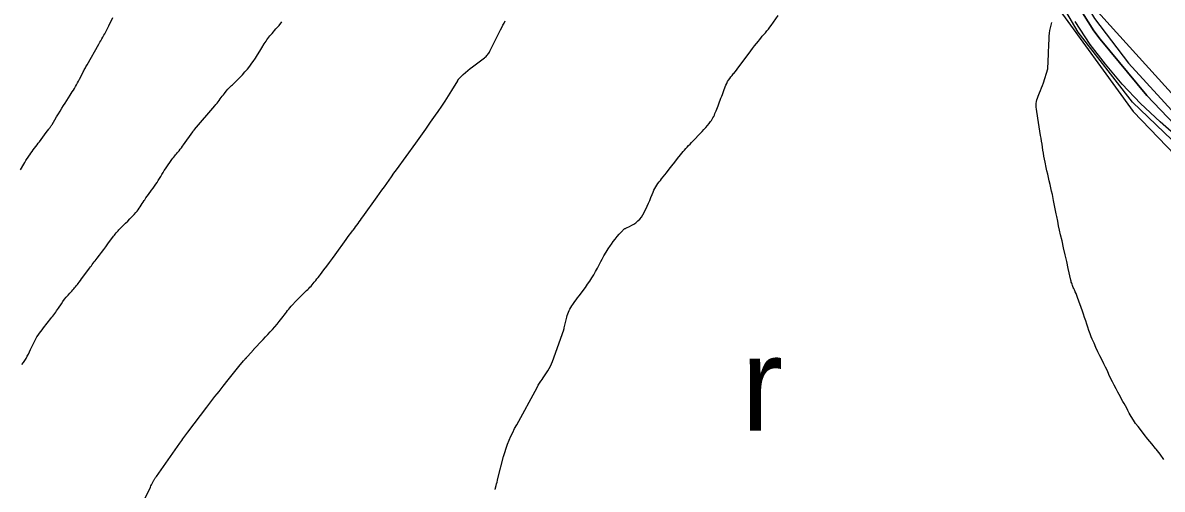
# Model space of a CAD drawing. Extents: x -629976 to -626966, y -1086511 to -1082952.
# Drawn here: x -629290.8 to -629035.3, y -1086079 to -1085974.4 of the extents above; entities that cross this region are included whole.
import ezdxf

# ---------------------------------------------------------------- set-up
doc = ezdxf.new("R2010")
doc.units = 0
for name, color, linetype in [('01_OBVOD PÚ', 7, 'Continuous'), ('01_PARCELY_NÁVRH_PC', 7, 'Continuous'), ('01_VRSTEVNICE', 7, 'Continuous'), ('02_KULTURY STAV', 7, 'Continuous'), ('03_PC_NÁVRH', 7, 'Continuous'), ('03_PC_OBJEKTY_NÁVRH', 7, 'Continuous'), ('04_ZPF_OP_ORGAN', 7, 'Continuous'), ('05_VHO_OPVZ', 7, 'Continuous')]:
    doc.layers.add(name, color=color, linetype=linetype)

msp = doc.modelspace()

# ---------------------------------------------------------------- linework, layer by layer
at = {"layer": '01_OBVOD PÚ'}
msp.add_lwpolyline([(-629150.28, -1085765.65), (-629148.72, -1085805.48), (-629141.31, -1085833.59), (-629128.11, -1085853.02), (-629125.94, -1085855.15), (-629104.39, -1085877.56), (-629101.39, -1085880.01), (-629093.2, -1085885.54), (-629081.1, -1085905.64), (-629071.96, -1085919.41), (-629058.85, -1085946.7), (-629049.68, -1085971.97), (-629047.7, -1085974.15), (-629031.77, -1085991.7), (-629013.43, -1086008.55), (-628996.23, -1086021.54), (-628982.57, -1086033.23), (-628979.99, -1086035.43), (-628963.86, -1086049.23), (-628947.04, -1086060.41), (-628925.53, -1086073.14), (-628892, -1086083.87)], dxfattribs=at)
at = {"layer": '01_PARCELY_NÁVRH_PC'}
for points in [[(-629011.89, -1086017.6), (-629035.76, -1085996.56), (-629040.17, -1085992.44), (-629044.28, -1085988.11), (-629048.06, -1085983.67), (-629051.43, -1085979.21), (-629054.85, -1085974.1)], [(-629047.7, -1085974.15), (-629031.77, -1085991.7)]]:
    msp.add_lwpolyline(points, dxfattribs=at)
at = {"layer": '01_VRSTEVNICE'}
for points in [[(-629291.33, -1086007.3), (-629290.62, -1086006.09), (-629290.37, -1086005.66), (-629290.11, -1086005.24), (-629289.84, -1086004.82), (-629289.57, -1086004.41), (-629289.53, -1086004.35), (-629289.27, -1086003.97), (-629289, -1086003.59), (-629288.73, -1086003.21), (-629288.46, -1086002.84), (-629288.18, -1086002.47), (-629287.91, -1086002.09), (-629287.63, -1086001.72), (-629287.35, -1086001.35), (-629287.1, -1086001.03), (-629286.71, -1086000.52), (-629286.33, -1086000.01), (-629285.94, -1085999.49), (-629285.56, -1085998.98), (-629284.98, -1085998.22), (-629284.88, -1085998.09), (-629284.79, -1085997.95), (-629284.69, -1085997.82), (-629284.6, -1085997.69), (-629284.51, -1085997.55), (-629284.42, -1085997.42), (-629284.34, -1085997.28), (-629284.25, -1085997.14), (-629283.63, -1085996.11), (-629283.24, -1085995.46), (-629282.84, -1085994.8), (-629282.44, -1085994.15), (-629282.04, -1085993.5), (-629281.69, -1085992.94), (-629281.32, -1085992.36), (-629280.95, -1085991.78), (-629280.58, -1085991.2), (-629280.21, -1085990.62), (-629279.97, -1085990.25), (-629279.72, -1085989.86), (-629279.47, -1085989.46), (-629279.22, -1085989.06), (-629278.98, -1085988.65), (-629278.75, -1085988.25), (-629278.52, -1085987.83), (-629278.3, -1085987.42), (-629278.09, -1085987), (-629277.38, -1085985.6), (-629277.27, -1085985.37), (-629277.15, -1085985.14), (-629277.03, -1085984.92), (-629276.91, -1085984.69), (-629276.79, -1085984.47), (-629276.67, -1085984.24), (-629276.55, -1085984.02), (-629276.42, -1085983.8), (-629273.76, -1085979.12), (-629273.55, -1085978.74), (-629273.33, -1085978.37), (-629273.11, -1085977.99), (-629272.89, -1085977.61), (-629272.8, -1085977.44), (-629272.63, -1085977.15), (-629272.46, -1085976.85), (-629272.29, -1085976.55), (-629272.12, -1085976.25), (-629271.96, -1085975.95), (-629271.8, -1085975.65), (-629271.65, -1085975.35), (-629271.5, -1085975.04), (-629270.6, -1085973.17)], [(-629291.01, -1086051.01), (-629290.68, -1086050.57), (-629290.37, -1086050.11), (-629290.09, -1086049.64), (-629289.82, -1086049.15), (-629289.57, -1086048.66), (-629289.33, -1086048.16), (-629289.09, -1086047.66), (-629288.85, -1086047.16), (-629288.37, -1086046.13), (-629288.15, -1086045.68), (-629287.91, -1086045.24), (-629287.65, -1086044.81), (-629287.38, -1086044.4), (-629287.1, -1086043.99), (-629286.81, -1086043.58), (-629286.5, -1086043.18), (-629286.2, -1086042.79), (-629284.5, -1086040.69), (-629284.28, -1086040.41), (-629284.06, -1086040.12), (-629283.85, -1086039.83), (-629283.65, -1086039.54), (-629283.44, -1086039.24), (-629283.24, -1086038.94), (-629283.04, -1086038.64), (-629282.84, -1086038.34), (-629282.16, -1086037.35), (-629281.81, -1086036.85), (-629281.44, -1086036.36), (-629281.06, -1086035.89), (-629280.66, -1086035.42), (-629280.27, -1086034.99), (-629280.06, -1086034.75), (-629279.84, -1086034.51), (-629279.62, -1086034.27), (-629279.41, -1086034.04), (-629279.19, -1086033.8), (-629278.98, -1086033.56), (-629278.78, -1086033.31), (-629278.58, -1086033.06), (-629278.43, -1086032.86), (-629278.16, -1086032.5), (-629277.9, -1086032.14), (-629277.63, -1086031.79), (-629277.37, -1086031.43), (-629275.88, -1086029.4), (-629275.66, -1086029.12), (-629275.45, -1086028.83), (-629275.23, -1086028.56), (-629275.01, -1086028.28), (-629274.79, -1086028), (-629274.57, -1086027.72), (-629274.36, -1086027.44), (-629274.14, -1086027.16), (-629273.62, -1086026.47), (-629273.14, -1086025.84), (-629272.67, -1086025.21), (-629272.2, -1086024.58), (-629271.73, -1086023.95), (-629270.47, -1086022.23), (-629270.28, -1086021.98), (-629270.08, -1086021.73), (-629269.88, -1086021.49), (-629269.68, -1086021.25), (-629269.47, -1086021.02), (-629269.26, -1086020.79), (-629269.04, -1086020.56), (-629268.82, -1086020.34), (-629267.77, -1086019.3), (-629267.28, -1086018.81), (-629266.8, -1086018.32), (-629266.32, -1086017.82), (-629265.85, -1086017.32), (-629265.48, -1086016.92), (-629265.21, -1086016.6), (-629264.95, -1086016.28), (-629264.7, -1086015.95), (-629264.47, -1086015.6), (-629264.25, -1086015.25), (-629264.02, -1086014.9), (-629263.8, -1086014.55), (-629263.57, -1086014.2), (-629263.48, -1086014.06), (-629263.21, -1086013.64), (-629262.92, -1086013.23), (-629262.63, -1086012.83), (-629262.33, -1086012.43), (-629262.27, -1086012.35), (-629261.93, -1086011.92), (-629261.61, -1086011.48), (-629261.29, -1086011.03), (-629260.99, -1086010.58), (-629260.72, -1086010.18), (-629260.44, -1086009.74), (-629260.16, -1086009.3), (-629259.9, -1086008.85), (-629259.63, -1086008.4), (-629259.37, -1086007.96), (-629259.1, -1086007.51), (-629258.81, -1086007.08), (-629258.52, -1086006.65), (-629257.57, -1086005.27), (-629257.38, -1086005), (-629257.18, -1086004.73), (-629256.97, -1086004.47), (-629256.76, -1086004.22), (-629256.54, -1086003.96), (-629256.32, -1086003.71), (-629256.11, -1086003.45), (-629255.9, -1086003.2), (-629255.78, -1086003.06), (-629255.52, -1086002.73), (-629255.26, -1086002.39), (-629255.01, -1086002.05), (-629254.76, -1086001.71), (-629252.68, -1085998.8), (-629252.66, -1085998.76), (-629252.63, -1085998.72), (-629252.6, -1085998.69), (-629252.58, -1085998.65), (-629252.55, -1085998.61), (-629252.54, -1085998.6), (-629252.53, -1085998.58), (-629252.52, -1085998.57), (-629252.51, -1085998.55), (-629252.5, -1085998.54), (-629252.49, -1085998.53), (-629252.48, -1085998.51), (-629252.47, -1085998.5), (-629252.42, -1085998.45), (-629252.39, -1085998.41), (-629252.36, -1085998.37), (-629252.33, -1085998.33), (-629252.29, -1085998.29), (-629247.75, -1085992.98), (-629247.5, -1085992.68), (-629247.26, -1085992.38), (-629247.02, -1085992.07), (-629246.79, -1085991.75), (-629246.56, -1085991.43), (-629246.33, -1085991.12), (-629246.09, -1085990.81), (-629245.85, -1085990.5), (-629245.6, -1085990.18), (-629245.23, -1085989.73), (-629244.84, -1085989.28), (-629244.43, -1085988.85), (-629244.01, -1085988.44), (-629243.8, -1085988.24), (-629243.27, -1085987.72), (-629242.74, -1085987.21), (-629242.22, -1085986.68), (-629241.71, -1085986.15), (-629241.57, -1085986.01), (-629241.01, -1085985.39), (-629240.46, -1085984.76), (-629239.94, -1085984.1), (-629239.45, -1085983.43), (-629239.16, -1085983.02), (-629238.65, -1085982.27), (-629238.16, -1085981.52), (-629237.68, -1085980.76), (-629237.21, -1085980), (-629236.67, -1085979.08), (-629236.47, -1085978.77), (-629236.28, -1085978.46), (-629236.07, -1085978.16), (-629235.85, -1085977.87), (-629235.63, -1085977.58), (-629235.4, -1085977.3), (-629235.16, -1085977.02), (-629234.92, -1085976.75), (-629234.04, -1085975.74), (-629233.36, -1085974.96), (-629232.7, -1085974.16)], [(-629263.63, -1086081.42), (-629262.22, -1086078.5), (-629262.08, -1086078.22), (-629261.94, -1086077.94), (-629261.8, -1086077.66), (-629261.66, -1086077.38), (-629261.51, -1086077.09), (-629261.44, -1086076.96), (-629261.37, -1086076.84), (-629261.29, -1086076.71), (-629261.21, -1086076.59), (-629261.12, -1086076.47), (-629261.04, -1086076.34), (-629260.95, -1086076.22), (-629260.87, -1086076.1), (-629255.58, -1086068.61), (-629255.36, -1086068.31), (-629255.14, -1086068), (-629254.93, -1086067.69), (-629254.71, -1086067.38), (-629254.49, -1086067.08), (-629254.27, -1086066.77), (-629254.05, -1086066.47), (-629253.82, -1086066.17), (-629249.56, -1086060.54), (-629249.11, -1086059.95), (-629248.65, -1086059.36), (-629248.19, -1086058.77), (-629247.73, -1086058.18), (-629247.27, -1086057.6), (-629246.81, -1086057.01), (-629246.34, -1086056.43), (-629245.88, -1086055.85), (-629244.78, -1086054.46), (-629244.18, -1086053.71), (-629243.57, -1086052.96), (-629242.97, -1086052.21), (-629242.36, -1086051.46), (-629241.3, -1086050.16), (-629241.22, -1086050.06), (-629241.14, -1086049.97), (-629241.05, -1086049.87), (-629240.97, -1086049.78), (-629240.92, -1086049.73), (-629240.86, -1086049.66), (-629240.8, -1086049.6), (-629240.74, -1086049.54), (-629240.68, -1086049.47), (-629240.62, -1086049.41), (-629240.56, -1086049.34), (-629240.51, -1086049.28), (-629240.45, -1086049.21), (-629239.04, -1086047.61), (-629238.99, -1086047.56), (-629238.95, -1086047.51), (-629238.9, -1086047.45), (-629238.85, -1086047.4), (-629238.81, -1086047.35), (-629238.76, -1086047.3), (-629238.71, -1086047.25), (-629238.66, -1086047.2), (-629237.44, -1086045.92), (-629236.91, -1086045.36), (-629236.37, -1086044.81), (-629235.85, -1086044.24), (-629235.32, -1086043.68), (-629234.8, -1086043.11), (-629234.29, -1086042.54), (-629233.8, -1086041.95), (-629233.31, -1086041.35), (-629232.7, -1086040.57), (-629232.44, -1086040.24), (-629232.19, -1086039.91), (-629231.94, -1086039.57), (-629231.69, -1086039.24), (-629231.44, -1086038.9), (-629231.19, -1086038.57), (-629230.92, -1086038.25), (-629230.64, -1086037.94), (-629229.35, -1086036.53), (-629228.92, -1086036.08), (-629228.49, -1086035.63), (-629228.04, -1086035.2), (-629227.58, -1086034.77), (-629227.2, -1086034.43), (-629226.93, -1086034.18), (-629226.67, -1086033.92), (-629226.42, -1086033.66), (-629226.17, -1086033.39), (-629225.93, -1086033.11), (-629225.69, -1086032.83), (-629225.46, -1086032.55), (-629225.23, -1086032.27), (-629225.13, -1086032.16), (-629224.86, -1086031.81), (-629224.59, -1086031.47), (-629224.32, -1086031.12), (-629224.05, -1086030.77), (-629223.29, -1086029.79), (-629222.65, -1086028.95), (-629222.01, -1086028.1), (-629221.39, -1086027.25), (-629220.77, -1086026.39), (-629218.32, -1086022.97), (-629217.97, -1086022.49), (-629217.62, -1086022.01), (-629217.26, -1086021.53), (-629216.91, -1086021.05), (-629216.74, -1086020.83), (-629216.47, -1086020.47), (-629216.19, -1086020.1), (-629215.92, -1086019.74), (-629215.64, -1086019.37), (-629215.37, -1086019), (-629215.1, -1086018.64), (-629214.83, -1086018.27), (-629214.56, -1086017.9), (-629211.35, -1086013.42), (-629210.81, -1086012.67), (-629210.27, -1086011.91), (-629209.73, -1086011.15), (-629209.19, -1086010.39), (-629208.66, -1086009.63), (-629208.12, -1086008.87), (-629207.58, -1086008.11), (-629207.04, -1086007.36), (-629202.71, -1086001.32), (-629201.59, -1085999.76), (-629200.47, -1085998.21), (-629199.36, -1085996.65), (-629198.25, -1085995.09), (-629197.64, -1085994.23), (-629196.85, -1085993.09), (-629196.08, -1085991.93), (-629195.34, -1085990.76), (-629194.62, -1085989.58), (-629193.3, -1085987.34), (-629193.25, -1085987.26), (-629193.21, -1085987.19), (-629193.16, -1085987.11), (-629193.11, -1085987.04), (-629193.06, -1085986.97), (-629193.01, -1085986.9), (-629192.95, -1085986.84), (-629192.89, -1085986.77), (-629192.04, -1085985.95), (-629191.54, -1085985.49), (-629191.03, -1085985.04), (-629190.51, -1085984.61), (-629189.97, -1085984.2), (-629187.29, -1085982.2), (-629187.1, -1085982.05), (-629186.92, -1085981.89), (-629186.75, -1085981.72), (-629186.59, -1085981.53), (-629186.44, -1085981.34), (-629186.3, -1085981.14), (-629186.18, -1085980.93), (-629186.06, -1085980.72), (-629183.93, -1085976.41), (-629183.68, -1085975.92), (-629183.43, -1085975.42), (-629183.17, -1085974.92), (-629182.91, -1085974.43), (-629182.64, -1085973.9)], [(-629184.9, -1086079), (-629184.87, -1086078.89), (-629184.84, -1086078.78), (-629184.81, -1086078.68), (-629184.67, -1086078.12), (-629184.57, -1086077.73), (-629184.47, -1086077.35), (-629184.38, -1086076.96), (-629184.28, -1086076.58), (-629183.01, -1086071.64), (-629182.75, -1086070.7), (-629182.46, -1086069.78), (-629182.13, -1086068.87), (-629181.77, -1086067.97), (-629181.37, -1086067.09), (-629180.96, -1086066.21), (-629180.52, -1086065.35), (-629180.07, -1086064.49), (-629175.49, -1086056.15), (-629175.22, -1086055.66), (-629174.93, -1086055.18), (-629174.62, -1086054.71), (-629174.3, -1086054.25), (-629174.29, -1086054.23), (-629173.98, -1086053.78), (-629173.67, -1086053.33), (-629173.37, -1086052.88), (-629173.08, -1086052.42), (-629173.05, -1086052.38), (-629172.76, -1086051.88), (-629172.5, -1086051.38), (-629172.27, -1086050.86), (-629172.06, -1086050.34), (-629169.51, -1086043.21), (-629169.49, -1086043.16), (-629169.47, -1086043.1), (-629169.46, -1086043.05), (-629169.44, -1086042.99), (-629169.43, -1086042.94), (-629169.42, -1086042.88), (-629169.4, -1086042.82), (-629169.39, -1086042.77), (-629168.85, -1086040.41), (-629168.75, -1086040.02), (-629168.63, -1086039.64), (-629168.48, -1086039.27), (-629168.32, -1086038.9), (-629168.13, -1086038.55), (-629167.94, -1086038.2), (-629167.72, -1086037.86), (-629167.49, -1086037.53), (-629167.34, -1086037.32), (-629167.03, -1086036.89), (-629166.71, -1086036.47), (-629166.4, -1086036.04), (-629166.08, -1086035.61), (-629164.65, -1086033.7), (-629164.16, -1086033.01), (-629163.68, -1086032.31), (-629163.23, -1086031.59), (-629162.8, -1086030.86), (-629162.39, -1086030.12), (-629161.98, -1086029.38), (-629161.58, -1086028.64), (-629161.18, -1086027.89), (-629160.92, -1086027.4), (-629160.49, -1086026.61), (-629160.03, -1086025.83), (-629159.55, -1086025.07), (-629159.05, -1086024.33), (-629158.82, -1086024.01), (-629158.41, -1086023.44), (-629157.98, -1086022.87), (-629157.53, -1086022.32), (-629157.07, -1086021.78), (-629156.29, -1086020.91), (-629156.2, -1086020.82), (-629156.11, -1086020.74), (-629156.01, -1086020.66), (-629155.91, -1086020.59), (-629155.8, -1086020.52), (-629155.7, -1086020.46), (-629155.59, -1086020.4), (-629155.47, -1086020.35), (-629154.73, -1086020.02), (-629154.26, -1086019.78), (-629153.81, -1086019.52), (-629153.38, -1086019.21), (-629152.98, -1086018.87), (-629152.89, -1086018.79), (-629152.48, -1086018.37), (-629152.11, -1086017.93), (-629151.79, -1086017.44), (-629151.51, -1086016.93), (-629150.84, -1086015.5), (-629150.54, -1086014.84), (-629150.24, -1086014.18), (-629149.96, -1086013.51), (-629149.69, -1086012.84), (-629149.48, -1086012.31), (-629149.3, -1086011.91), (-629149.11, -1086011.51), (-629148.88, -1086011.13), (-629148.64, -1086010.77), (-629148.38, -1086010.41), (-629148.11, -1086010.05), (-629147.84, -1086009.7), (-629147.57, -1086009.35), (-629146.48, -1086007.98), (-629145.86, -1086007.19), (-629145.24, -1086006.41), (-629144.62, -1086005.62), (-629144, -1086004.83), (-629143.34, -1086003.97), (-629143.05, -1086003.61), (-629142.76, -1086003.26), (-629142.45, -1086002.91), (-629142.14, -1086002.57), (-629141.82, -1086002.24), (-629141.51, -1086001.91), (-629141.19, -1086001.57), (-629140.87, -1086001.24), (-629138.48, -1085998.75), (-629138.07, -1085998.31), (-629137.67, -1085997.86), (-629137.29, -1085997.4), (-629136.92, -1085996.93), (-629136.61, -1085996.52), (-629136.41, -1085996.24), (-629136.22, -1085995.95), (-629136.05, -1085995.65), (-629135.89, -1085995.35), (-629135.74, -1085995.04), (-629135.6, -1085994.72), (-629135.47, -1085994.4), (-629135.34, -1085994.09), (-629134.89, -1085992.96), (-629134.73, -1085992.54), (-629134.56, -1085992.12), (-629134.4, -1085991.7), (-629134.25, -1085991.27), (-629134.09, -1085990.85), (-629133.93, -1085990.43), (-629133.78, -1085990.01), (-629133.62, -1085989.58), (-629133.31, -1085988.72), (-629133.15, -1085988.33), (-629132.97, -1085987.94), (-629132.76, -1085987.56), (-629132.54, -1085987.2), (-629132.29, -1085986.84), (-629132.04, -1085986.49), (-629131.77, -1085986.16), (-629131.49, -1085985.83), (-629131.4, -1085985.73), (-629131.07, -1085985.35), (-629130.76, -1085984.97), (-629130.45, -1085984.57), (-629130.15, -1085984.17), (-629127.58, -1085980.65), (-629127.17, -1085980.09), (-629126.74, -1085979.54), (-629126.31, -1085978.99), (-629125.87, -1085978.45), (-629125.65, -1085978.18), (-629125.31, -1085977.78), (-629124.98, -1085977.38), (-629124.64, -1085976.98), (-629124.3, -1085976.59), (-629123.96, -1085976.19), (-629123.63, -1085975.78), (-629123.31, -1085975.36), (-629123, -1085974.94), (-629121.4, -1085972.71)], [(-629034.92, -1086072.29), (-629035.79, -1086071.13), (-629036.68, -1086069.98), (-629036.82, -1086069.8), (-629037.66, -1086068.76), (-629038.5, -1086067.71), (-629039.34, -1086066.65), (-629040.18, -1086065.6), (-629040.72, -1086064.92), (-629041.26, -1086064.2), (-629041.78, -1086063.45), (-629042.25, -1086062.68), (-629042.69, -1086061.89), (-629042.99, -1086061.34), (-629043.26, -1086060.81), (-629043.54, -1086060.29), (-629043.83, -1086059.77), (-629044.12, -1086059.25), (-629044.4, -1086058.73), (-629044.69, -1086058.21), (-629044.97, -1086057.69), (-629045.26, -1086057.16), (-629045.66, -1086056.42), (-629046.08, -1086055.63), (-629046.48, -1086054.84), (-629046.87, -1086054.04), (-629047.24, -1086053.23), (-629047.61, -1086052.43), (-629047.99, -1086051.62), (-629048.38, -1086050.82), (-629048.78, -1086050.03), (-629049.28, -1086049.04), (-629049.73, -1086048.12), (-629050.17, -1086047.18), (-629050.59, -1086046.24), (-629051, -1086045.29), (-629051.21, -1086044.8), (-629051.49, -1086044.09), (-629051.76, -1086043.37), (-629052.01, -1086042.65), (-629052.24, -1086041.92), (-629052.47, -1086041.19), (-629052.71, -1086040.46), (-629052.95, -1086039.73), (-629053.21, -1086039.01), (-629054.3, -1086035.94), (-629054.46, -1086035.52), (-629054.62, -1086035.1), (-629054.8, -1086034.69), (-629054.98, -1086034.28), (-629055.15, -1086033.93), (-629055.25, -1086033.7), (-629055.35, -1086033.47), (-629055.44, -1086033.24), (-629055.53, -1086033), (-629055.61, -1086032.76), (-629055.69, -1086032.52), (-629055.75, -1086032.28), (-629055.81, -1086032.04), (-629056.38, -1086029.45), (-629056.72, -1086027.91), (-629057.07, -1086026.37), (-629057.41, -1086024.83), (-629057.76, -1086023.29), (-629058.08, -1086021.93), (-629058.31, -1086020.9), (-629058.54, -1086019.86), (-629058.75, -1086018.83), (-629058.97, -1086017.79), (-629059.09, -1086017.18), (-629059.24, -1086016.44), (-629059.39, -1086015.71), (-629059.53, -1086014.97), (-629059.68, -1086014.23), (-629059.94, -1086012.89), (-629060.1, -1086012.12), (-629060.26, -1086011.36), (-629060.44, -1086010.59), (-629060.62, -1086009.83), (-629060.8, -1086009.07), (-629060.98, -1086008.31), (-629061.16, -1086007.55), (-629061.33, -1086006.78), (-629061.58, -1086005.63), (-629061.72, -1086004.96), (-629061.85, -1086004.29), (-629061.96, -1086003.62), (-629062.06, -1086002.95), (-629062.16, -1086002.27), (-629062.26, -1086001.6), (-629062.36, -1086000.93), (-629062.47, -1086000.26), (-629062.57, -1085999.65), (-629062.74, -1085998.67), (-629062.9, -1085997.69), (-629063.05, -1085996.71), (-629063.2, -1085995.73), (-629063.52, -1085993.7), (-629063.56, -1085993.28), (-629063.57, -1085992.87), (-629063.55, -1085992.45), (-629063.49, -1085992.04), (-629063.4, -1085991.63), (-629063.29, -1085991.23), (-629063.15, -1085990.83), (-629062.99, -1085990.44), (-629062.84, -1085990.09), (-629062.59, -1085989.53), (-629062.36, -1085988.97), (-629062.16, -1085988.39), (-629061.96, -1085987.81), (-629060.98, -1085984.67), (-629060.98, -1085984.66), (-629060.97, -1085984.66), (-629060.97, -1085984.65), (-629060.97, -1085984.64), (-629060.96, -1085984.63), (-629060.96, -1085984.62), (-629060.96, -1085984.61), (-629060.96, -1085984.6), (-629060.96, -1085984.59), (-629060.96, -1085984.59), (-629060.96, -1085984.58), (-629060.81, -1085981.38), (-629060.78, -1085980.6), (-629060.75, -1085979.83), (-629060.72, -1085979.05), (-629060.69, -1085978.27), (-629060.68, -1085977.96), (-629060.65, -1085977.34), (-629060.59, -1085976.72), (-629060.49, -1085976.1), (-629060.37, -1085975.49), (-629060.22, -1085974.88), (-629060.04, -1085974.28)]]:
    msp.add_lwpolyline(points, dxfattribs=at)
at = {"layer": '02_KULTURY STAV'}
for points in [[(-629315.26, -1085933.92), (-629290.08, -1085888.82), (-629270.79, -1085881.81), (-629263.62, -1085878.44), (-629256.36, -1085875.28), (-629248.54, -1085873.03), (-629222.32, -1085865.34), (-629205.81, -1085859.65), (-629187.37, -1085853.31), (-629177.06, -1085850.52), (-629170.23, -1085849.64), (-629153.55, -1085848.3), (-629142.1, -1085849.52), (-629132.11, -1085854.87), (-629103.36, -1085887.17), (-629090.79, -1085901.96), (-629084.11, -1085913.46), (-629066.15, -1085950.26), (-629060.06, -1085961.14), (-629050.66, -1085976.16), (-629049.21, -1085978), (-629038.79, -1085990.64), (-629026.26, -1086003.71)], [(-629026.26, -1086003.71), (-629038.79, -1085990.64), (-629049.21, -1085978), (-629050.66, -1085976.16), (-629060.06, -1085961.14)], [(-629047.7, -1085974.15), (-629031.77, -1085991.7)]]:
    msp.add_lwpolyline(points, dxfattribs=at)
at = {"layer": '03_PC_NÁVRH'}
msp.add_lwpolyline([(-629286.99, -1085878.56), (-629277.57, -1085879.34), (-629247.38, -1085869.31), (-629224.9, -1085863.28), (-629187.9, -1085850.45), (-629171.53, -1085845.18), (-629154.96, -1085842.99), (-629143.01, -1085845.95), (-629136.17, -1085848.96), (-629128.63, -1085856.25), (-629096.38, -1085892.7), (-629090.03, -1085899.57), (-629083.28, -1085910.95), (-629068.35, -1085941.63), (-629060.96, -1085956.05), (-629050.49, -1085973.39), (-629042.87, -1085983.42), (-629026.75, -1086001.05), (-629012.3, -1086014.17), (-628978.5, -1086043.67), (-628964.8, -1086054.37), (-628951.02, -1086063.21), (-628916.5, -1086080.73)], dxfattribs=at)
at = {"layer": '03_PC_OBJEKTY_NÁVRH'}
msp.add_lwpolyline([(-628922.38, -1086082.81), (-628949.48, -1086068.21), (-628977.67, -1086049.64), (-628989.98, -1086039.8), (-629020.84, -1086012.44), (-629041.95, -1085992.17), (-629054.17, -1085976.5), (-629063.94, -1085959.73), (-629075.97, -1085934.74), (-629088.85, -1085908.52), (-629102.07, -1085893.19), (-629120.56, -1085871.66), (-629135.92, -1085854.46), (-629145.31, -1085848.87), (-629153.88, -1085847.41), (-629167.21, -1085848.29), (-629176.98, -1085843.08), (-629228.21, -1085860.22), (-629267.42, -1085871.15)], dxfattribs=at)
at = {"layer": '04_ZPF_OP_ORGAN'}
msp.add_lwpolyline([(-629315.26, -1085933.92), (-629290.08, -1085888.82), (-629270.79, -1085881.81), (-629263.62, -1085878.44), (-629256.36, -1085875.28), (-629248.54, -1085873.03), (-629222.32, -1085865.34), (-629205.81, -1085859.65), (-629187.37, -1085853.31), (-629177.06, -1085850.52), (-629170.23, -1085849.64), (-629153.55, -1085848.3), (-629142.1, -1085849.52), (-629132.11, -1085854.87), (-629103.36, -1085887.17), (-629090.79, -1085901.96), (-629084.11, -1085913.46), (-629066.15, -1085950.26), (-629060.06, -1085961.14), (-629050.66, -1085976.16), (-629049.21, -1085978), (-629038.79, -1085990.64), (-629026.26, -1086003.71)], dxfattribs=at)
at = {"layer": '05_VHO_OPVZ'}
msp.add_lwpolyline([(-629305.49, -1085879.25), (-629271.69, -1085872.49), (-629234.13, -1085873.24), (-629189.81, -1085882.25), (-629113.19, -1085902.54), (-629090.65, -1085916.82), (-629074.12, -1085941.62), (-629059.85, -1085969.42), (-629041.82, -1085994.22), (-629023.04, -1086013.75), (-628993, -1086040.05), (-628953.94, -1086069.36), (-628925.39, -1086084.39), (-628898.35, -1086096.41), (-628881.07, -1086102.42), (-628845.01, -1086109.18), (-628820.22, -1086122.71), (-628788.67, -1086143.75), (-628757.88, -1086163.28), (-628730.08, -1086183.57), (-628710.52, -1086200.08), (-628883.14, -1086510.63)], dxfattribs=at)

# ---------------------------------------------------------------- texts
at = {"layer": '02_KULTURY STAV'}
msp.add_text('r', height=21, dxfattribs=at).set_placement((-629129.69, -1086065.82))

doc.saveas('drawing.dxf')
